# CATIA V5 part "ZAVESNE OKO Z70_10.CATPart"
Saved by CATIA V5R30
Part number: ZAVESNE OKO Z70/10
Bounding box of the stored display mesh (mm): x -45 to 17, y -22.495 to 22.495, z -12.5 to 12.5
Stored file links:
  C:\Users\ondra\Desktop\PŘÍLOHA P III\CATIA\ZAVESNE OKO Z70_10.CATPart
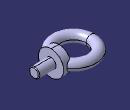
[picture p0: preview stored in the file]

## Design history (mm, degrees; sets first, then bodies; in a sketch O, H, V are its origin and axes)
Set1
  DatumSurface1 to DatumSurface18 " Z710/10"
  Join1: Elements (DatumSurface1; DatumSurface2; DatumSurface3; DatumSurface4; DatumSurface5; DatumSurface6; DatumSurface7; DatumSurface8; DatumSurface9; DatumSurface10; DatumSurface11; DatumSurface12; DatumSurface13; DatumSurface14; DatumSurface15; DatumSurface16; DatumSurface17; DatumSurface18)
Body1 (main body)
  CloseSurface1: CloseElement Join1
